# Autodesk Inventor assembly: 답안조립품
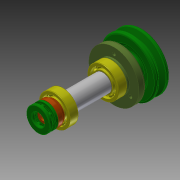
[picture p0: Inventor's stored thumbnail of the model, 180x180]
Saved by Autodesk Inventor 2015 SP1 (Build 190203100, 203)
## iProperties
Created: 2017-09
Part Number: 답안조립품
Document SubType Name: Assembly
Designer: C04
Author: C04
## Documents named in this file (10)
- C:\Users\C04\Desktop\답안조립품.iam
- C:\Users\C04\Desktop\본체.ipt
- C:\Users\C04\Desktop\커버.ipt
- C:\Users\C04\Desktop\오일 실 20x35x7.ipt
- C:\Users\C04\Desktop\베어링 6004.ipt
- C:\Users\C04\Desktop\축.ipt
- C:\Users\C04\Desktop\키 5 x 5 x 16.ipt
- C:\Users\C04\Desktop\V벨트풀리.ipt
- C:\Users\C04\Desktop\어댑터슬리브.ipt
- C:\Users\C04\Desktop\베어링 51202.ipt
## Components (1 placed, 1 different names)
1. V벨트풀리:1 — 각도:1
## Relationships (1: Angle 1)
- 각도:1 [Angle]: V벨트풀리:1
